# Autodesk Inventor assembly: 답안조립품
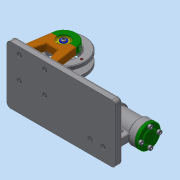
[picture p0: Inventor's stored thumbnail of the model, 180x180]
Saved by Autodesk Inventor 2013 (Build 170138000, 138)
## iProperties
Created: 2018-01
Part Number: 답안조립품
Document SubType Name: Assembly
Designer: dgall
Author: dgall
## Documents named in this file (19)
- C:\Users\dgall\Desktop\380107V1030\답안조립품.iam
- C:\Users\dgall\Desktop\380107V1030\플레이트.ipt
- C:\Users\dgall\Desktop\380107V1030\지지대-A.ipt
- C:\Users\dgall\Desktop\380107V1030\V-벨트풀리.ipt
- C:\Users\dgall\Desktop\380107V1030\스페이서.ipt
- C:\Users\dgall\Desktop\380107V1030\베어링 8x22x7.ipt
- C:\Users\dgall\Desktop\380107V1030\크랭크축.ipt
- C:\Users\dgall\Desktop\380107V1030\3mm 와셔.ipt
- C:\Users\dgall\Desktop\380107V1030\볼트 M3x8.ipt
- C:\Users\dgall\Desktop\380107V1030\베어링커버-A.ipt
- C:\Users\dgall\Desktop\380107V1030\둥근머리볼트 M3x12.ipt
- C:\Users\dgall\Desktop\380107V1030\커넥팅로드-A.ipt
- C:\Users\dgall\Desktop\380107V1030\플랜지.ipt
- C:\Users\dgall\Desktop\380107V1030\볼트 M3x12.ipt
- C:\Users\dgall\Desktop\380107V1030\하우징.ipt
- C:\Users\dgall\Desktop\380107V1030\하우징커버-B.ipt
- C:\Users\dgall\Desktop\380107V1030\피스톤.ipt
- C:\Users\dgall\Desktop\380107V1030\하우징커버-A.ipt
- C:\Users\dgall\Desktop\380107V1030\커넥팅로드-B.ipt
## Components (9 placed, 8 different names)
1. 플레이트:1
2. V-벨트풀리:1
3. 3mm 와셔:1
4. 3mm 와셔:2
5. 플랜지:1
6. 하우징:1
7. 하우징커버-B:1
8. 피스톤:1
9. 하우징커버-A:1
